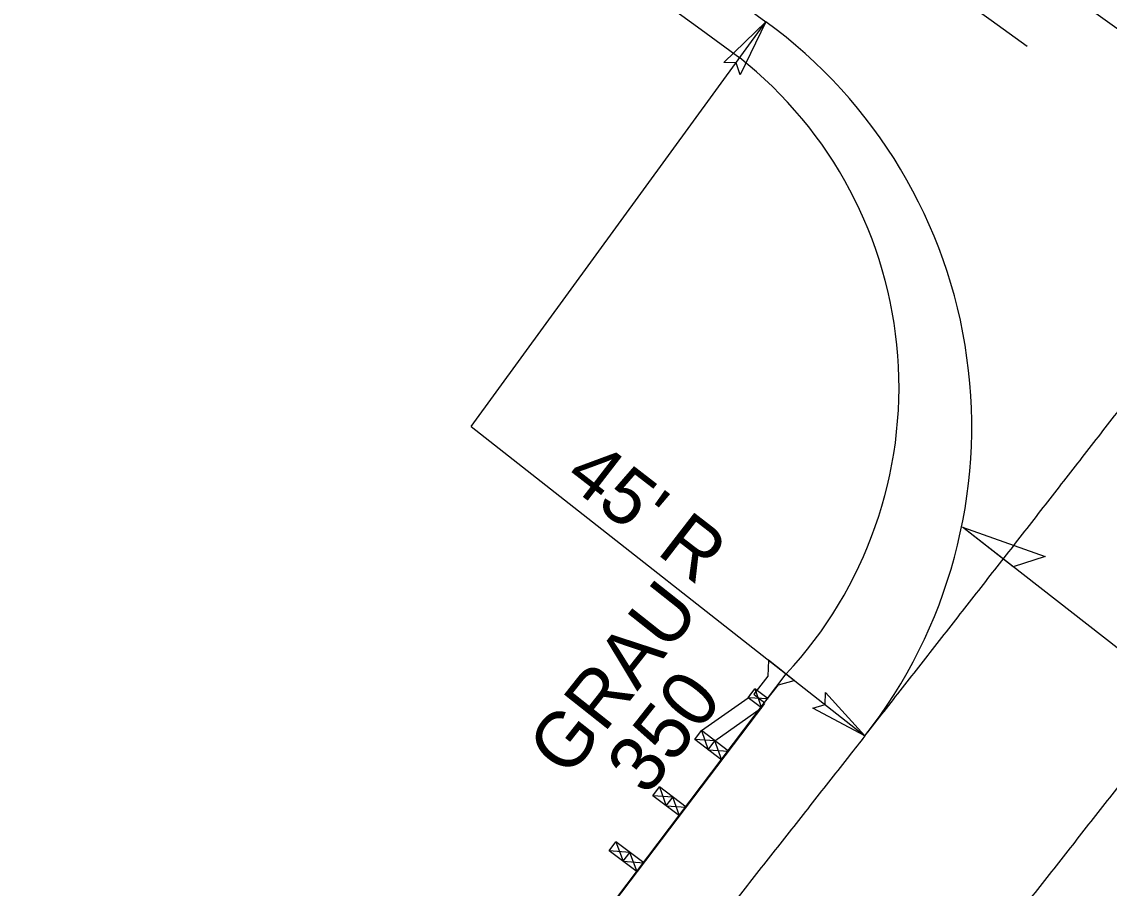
# Model space of a CAD drawing. Extents: x 1778969 to 1790720, y 807089 to 817794.
# Drawn here: x 1782430.2 to 1782528, y 814286.7 to 814364.6 of the extents above; entities that cross this region are included whole.
import ezdxf

# ---------------------------------------------------------------- set-up
doc = ezdxf.new("R2010")
doc.units = 0
for name, color, linetype in [('Prop CMT Guardrail Graphics', 7, 'Continuous'), ('Prop Dimension', 7, 'Continuous'), ('Prop Dimension Text', 7, 'Continuous'), ('Prop EOT', 7, 'Continuous'), ('Prop Guardrail Anchor Unit CELL', 7, 'Continuous'), ('Prop Horizontal Alignment', 7, 'Continuous'), ('Prop Lane Lines', 7, 'Continuous'), ('Prop Paved Shoulder', 7, 'Continuous'), ('Prop Superelevation  Arrow CELL', 7, 'Continuous'), ('Prop Terminator CELL', 7, 'Continuous'), ('Scratch_Level_2', 7, 'Continuous')]:
    doc.layers.add(name, color=color, linetype=linetype)

msp = doc.modelspace()

# ---------------------------------------------------------------- linework, layer by layer
at = {"layer": 'Prop CMT Guardrail Graphics'}
msp.add_line((1782468.979, 814266.359), (1782498.95, 814305.949), dxfattribs=at)
at = {"layer": 'Prop Dimension'}
for p, q in [((1782470.634, 814328.179), (1782497.128, 814364.553)), ((1782470.637, 814328.183), (1782506.028, 814300.39))]:
    msp.add_line(p, q, dxfattribs=at)
at = {"layer": 'Prop EOT'}
for centre, radius, start, end in [((1784215.136, 816723.191), 2918, 223.167897, 233.930786), ((1782470.634, 814328.179), 45, 321.86374, 53.93079)]:
    msp.add_arc(centre, radius, start, end, dxfattribs=at)
msp.add_spline([(1782506.028, 814300.39), (1782504.635, 814298.616), (1782502.969, 814296.496), (1782501.303, 814294.377), (1782499.635, 814292.258), (1782497.967, 814290.139), (1782496.298, 814288.021), (1782494.628, 814285.902), (1782492.958, 814283.784), (1782491.287, 814281.666), (1782489.615, 814279.548), (1782487.942, 814277.43), (1782486.269, 814275.312), (1782484.595, 814273.195), (1782482.921, 814271.077), (1782481.246, 814268.959), (1782479.571, 814266.841), (1782477.896, 814264.723), (1782476.22, 814262.605), (1782474.543, 814260.487), (1782472.866, 814258.369), (1782471.189, 814256.251), (1782469.512, 814254.132), (1782467.835, 814252.013)], degree=3, dxfattribs=at)
at = {"layer": 'Prop Guardrail Anchor Unit CELL'}
for p, q in [((1782497.364, 814307.199), (1782497.307, 814305.743)), ((1782499.672, 814305.378), (1782497.364, 814307.199)), ((1782497.307, 814305.743), (1782496.04, 814304.136)), ((1782497.001, 814303.38), (1782498.268, 814304.988)), ((1782498.268, 814304.988), (1782499.672, 814305.378)), ((1782491.335, 814300.861), (1782495.544, 814303.818)), ((1782495.544, 814303.818), (1782496.149, 814304.615)), ((1782495.544, 814303.818), (1782495.846, 814304.216)), ((1782496.739, 814302.911), (1782495.544, 814303.818)), ((1782497.344, 814303.707), (1782495.544, 814303.818)), ((1782496.04, 814304.136), (1782496.521, 814303.758)), ((1782497.344, 814303.707), (1782496.149, 814304.615)), ((1782496.149, 814304.615), (1782496.739, 814302.911)), ((1782496.521, 814303.758), (1782497.001, 814303.38)), ((1782468.766, 814266.078), (1782497.041, 814303.309)), ((1782492.555, 814299.935), (1782496.739, 814302.911)), ((1782490.73, 814300.064), (1782491.335, 814300.861)), ((1782493.775, 814299.008), (1782491.335, 814300.861)), ((1782491.335, 814300.861), (1782491.95, 814299.138)), ((1782493.17, 814298.211), (1782490.73, 814300.064)), ((1782492.555, 814299.935), (1782490.73, 814300.064)), ((1782491.95, 814299.138), (1782492.555, 814299.935)), ((1782493.17, 814298.211), (1782492.555, 814299.935)), ((1782491.95, 814299.138), (1782493.775, 814299.008)), ((1782486.97, 814295.007), (1782487.575, 814295.804)), ((1782489.359, 814293.193), (1782486.97, 814295.007)), ((1782488.769, 814294.897), (1782486.97, 814295.007)), ((1782489.964, 814293.99), (1782487.575, 814295.804)), ((1782487.575, 814295.804), (1782488.164, 814294.101)), ((1782488.164, 814294.101), (1782488.769, 814294.897)), ((1782488.164, 814294.101), (1782489.964, 814293.99)), ((1782489.359, 814293.193), (1782488.769, 814294.897)), ((1782483.049, 814290.072), (1782483.654, 814290.869)), ((1782485.548, 814288.175), (1782483.049, 814290.072)), ((1782484.903, 814289.92), (1782483.049, 814290.072)), ((1782486.152, 814288.972), (1782483.654, 814290.869)), ((1782483.654, 814290.869), (1782484.298, 814289.123)), ((1782484.298, 814289.123), (1782484.903, 814289.92)), ((1782484.298, 814289.123), (1782486.152, 814288.972)), ((1782485.548, 814288.175), (1782484.903, 814289.92))]:
    msp.add_line(p, q, dxfattribs=at)
at = {"layer": 'Prop Horizontal Alignment'}
msp.add_arc((1784215.136, 816723.191), 2900, 214.799146, 237.403945, dxfattribs=at)
msp.add_spline([(1782484.103, 814239.133), (1782485.781, 814241.252), (1782487.458, 814243.371), (1782489.136, 814245.49), (1782490.813, 814247.609), (1782492.491, 814249.729), (1782494.168, 814251.848), (1782495.845, 814253.967), (1782497.522, 814256.087), (1782499.198, 814258.207), (1782500.874, 814260.327), (1782502.55, 814262.448), (1782504.225, 814264.569), (1782505.9, 814266.69), (1782507.575, 814268.811), (1782509.249, 814270.933), (1782510.923, 814273.055), (1782512.596, 814275.177), (1782514.268, 814277.3), (1782515.94, 814279.424), (1782517.612, 814281.548), (1782519.282, 814283.672), (1782520.952, 814285.798), (1782522.621, 814287.923), (1782524.29, 814290.049), (1782525.958, 814292.176), (1782527.624, 814294.304), (1782529.29, 814296.432), (1782530.955, 814298.561), (1782532.619, 814300.691), (1782534.283, 814302.821), (1782535.945, 814304.952), (1782537.606, 814307.084), (1782539.266, 814309.217), (1782540.925, 814311.351), (1782542.583, 814313.485), (1782544.239, 814315.621), (1782545.895, 814317.757), (1782547.549, 814319.894), (1782549.202, 814322.033), (1782550.853, 814324.172), (1782552.504, 814326.312), (1782554.152, 814328.454), (1782555.8, 814330.596), (1782557.446, 814332.74), (1782559.09, 814334.885), (1782560.733, 814337.031), (1782562.375, 814339.178), (1782564.015, 814341.326), (1782565.653, 814343.476), (1782567.29, 814345.627), (1782568.925, 814347.779), (1782570.558, 814349.932), (1782572.189, 814352.087), (1782573.819, 814354.243), (1782575.447, 814356.4), (1782577.073, 814358.559), (1782578.697, 814360.72), (1782580.319, 814362.881), (1782581.939, 814365.045), (1782583.558, 814367.209), (1782585.174, 814369.376), (1782586.788, 814371.543), (1782588.4, 814373.713), (1782590.01, 814375.884), (1782591.617, 814378.056), (1782593.223, 814380.23), (1782594.826, 814382.406), (1782596.427, 814384.584), (1782598.025, 814386.763), (1782599.622, 814388.944), (1782601.216, 814391.127), (1782602.807, 814393.311), (1782604.396, 814395.498), (1782605.982, 814397.686)], degree=3, dxfattribs=at)
at = {"layer": 'Prop Lane Lines'}
msp.add_arc((1784215.136, 816723.191), 2906, 224.254541, 234.330695, dxfattribs=at)
msp.add_open_spline([(1782490.964, 814233.702), (1782491.523, 814234.408), (1782492.082, 814235.114), (1782492.641, 814235.821), (1782493.2, 814236.527), (1782493.76, 814237.234), (1782494.319, 814237.94), (1782494.878, 814238.646), (1782495.437, 814239.353), (1782495.997, 814240.059), (1782496.556, 814240.766), (1782497.115, 814241.472), (1782497.674, 814242.179), (1782498.234, 814242.885), (1782498.793, 814243.592), (1782499.352, 814244.299), (1782499.911, 814245.005), (1782500.471, 814245.712), (1782501.03, 814246.419), (1782501.589, 814247.125), (1782502.148, 814247.832), (1782502.707, 814248.539), (1782503.266, 814249.246), (1782503.825, 814249.952), (1782504.384, 814250.659), (1782504.944, 814251.366), (1782505.503, 814252.073), (1782506.062, 814252.78), (1782506.621, 814253.487), (1782507.18, 814254.194), (1782507.739, 814254.901), (1782508.298, 814255.609), (1782508.856, 814256.316), (1782509.415, 814257.023), (1782509.974, 814257.73), (1782510.533, 814258.438), (1782511.092, 814259.145), (1782511.65, 814259.852), (1782512.209, 814260.56), (1782512.768, 814261.267), (1782513.326, 814261.975), (1782513.885, 814262.683), (1782514.444, 814263.39), (1782515.002, 814264.098), (1782515.561, 814264.806), (1782516.119, 814265.514), (1782516.677, 814266.221), (1782517.236, 814266.929), (1782517.794, 814267.637), (1782518.352, 814268.345), (1782518.91, 814269.053), (1782519.468, 814269.762), (1782520.026, 814270.47), (1782520.584, 814271.178), (1782521.142, 814271.887), (1782521.7, 814272.595), (1782522.258, 814273.303), (1782522.816, 814274.012), (1782523.374, 814274.721), (1782523.931, 814275.429), (1782524.489, 814276.138), (1782525.046, 814276.847), (1782525.604, 814277.556), (1782526.161, 814278.265), (1782526.719, 814278.974), (1782527.276, 814279.683), (1782527.833, 814280.392), (1782528.39, 814281.102), (1782528.947, 814281.811), (1782529.504, 814282.52), (1782530.061, 814283.23), (1782530.618, 814283.939), (1782531.175, 814284.649), (1782531.731, 814285.359), (1782532.288, 814286.069), (1782532.844, 814286.779), (1782533.401, 814287.489), (1782533.957, 814288.199), (1782534.513, 814288.909), (1782535.069, 814289.619), (1782535.626, 814290.329), (1782536.181, 814291.04), (1782536.737, 814291.75), (1782537.293, 814292.461), (1782537.849, 814293.172), (1782538.404, 814293.883), (1782538.96, 814294.593), (1782539.515, 814295.305), (1782539.831, 814295.709), (1782540.147, 814296.113), (1782540.462, 814296.517)], degree=3, dxfattribs=at)
at = {"layer": 'Prop Paved Shoulder'}
msp.add_line((1782468.979, 814266.359), (1782498.95, 814305.949), dxfattribs=at)
for centre, radius, start, end in [((1784215.136, 816723.191), 2922, 223.167897, 233.930786), ((1782471.324, 814331.708), 37.772, 317.0035, 51.62465)]:
    msp.add_arc(centre, radius, start, end, dxfattribs=at)
at = {"layer": 'Prop Superelevation  Arrow CELL'}
msp.add_line((1782552.727, 814289.551), (1782514.794, 814319.141), dxfattribs=at)
msp.add_lwpolyline([(1782514.794, 814319.141), (1782522.246, 814316.499), (1782519.353, 814315.585)], close=True, dxfattribs=at)
at = {"layer": 'Prop Terminator CELL'}
for points in [[(1782493.354, 814360.888), (1782497.128, 814364.553), (1782494.804, 814359.797), (1782494.449, 814360.875)], [(1782502.503, 814304.294), (1782506.028, 814300.39), (1782501.359, 814302.885), (1782502.449, 814303.2)]]:
    msp.add_lwpolyline(points, close=True, dxfattribs=at)
at = {"layer": 'Scratch_Level_2'}
msp.add_spline([(1782506.028, 814300.39), (1782506.3, 814300.736), (1782507.963, 814302.856), (1782509.626, 814304.976), (1782511.288, 814307.097), (1782512.948, 814309.219), (1782514.608, 814311.341), (1782516.266, 814313.463), (1782517.923, 814315.586), (1782519.58, 814317.709), (1782521.234, 814319.833), (1782522.888, 814321.958), (1782524.54, 814324.083), (1782526.191, 814326.208), (1782527.841, 814328.335), (1782529.489, 814330.462), (1782531.135, 814332.589), (1782532.781, 814334.718), (1782534.424, 814336.847), (1782536.067, 814338.977), (1782537.707, 814341.108), (1782539.346, 814343.239), (1782540.984, 814345.372), (1782542.619, 814347.505), (1782544.253, 814349.639), (1782545.886, 814351.774), (1782547.516, 814353.91), (1782549.145, 814356.047), (1782550.772, 814358.185), (1782552.397, 814360.324), (1782554.02, 814362.464), (1782555.641, 814364.606), (1782557.26, 814366.748), (1782558.878, 814368.891), (1782560.493, 814371.036), (1782562.106, 814373.181), (1782563.717, 814375.328), (1782565.325, 814377.476), (1782566.932, 814379.625), (1782568.536, 814381.776), (1782570.139, 814383.927), (1782571.738, 814386.08), (1782573.336, 814388.235), (1782574.931, 814390.391), (1782576.524, 814392.548), (1782578.114, 814394.706), (1782579.702, 814396.866), (1782581.288, 814399.027), (1782582.871, 814401.19), (1782583.367, 814401.869)], degree=3, dxfattribs=at)

# ---------------------------------------------------------------- texts
at = {"layer": 'Prop Dimension Text'}
msp.add_text("45' R", height=5, rotation=322.27974, dxfattribs=at).set_placement((1782478.838, 814323.284))
at = {"layer": 'Prop Guardrail Anchor Unit CELL'}
for s, p in [('GRAU', (1782479.339, 814296.492)), ('350', (1782486.423, 814294.88))]:
    msp.add_text(s, height=5, rotation=51.63093, dxfattribs=at).set_placement(p)

doc.saveas('drawing.dxf')
